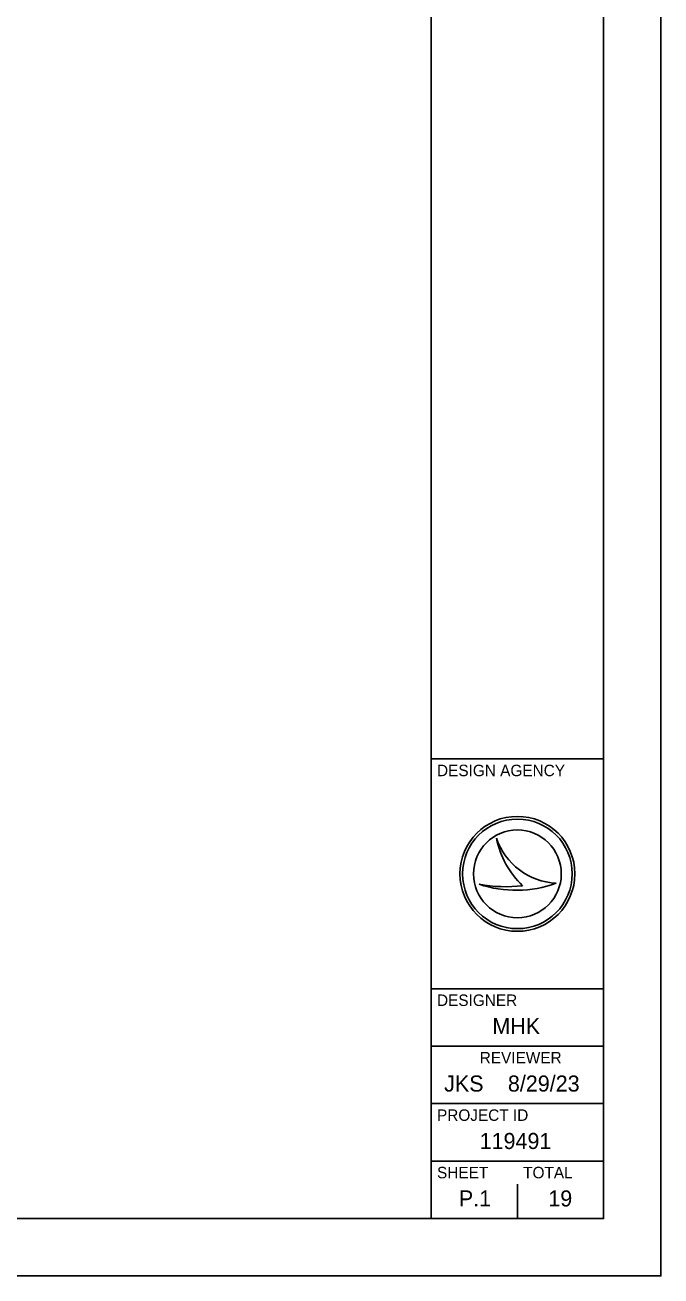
# Model space of a CAD drawing. Extents: x 0 to 34, y 0 to 22.
# Drawn here: x 28.46 to 34, y 0 to 10.89 of the extents above; entities that cross this region are included whole.
import ezdxf

# ---------------------------------------------------------------- set-up
doc = ezdxf.new("R2010")
doc.units = 0
for name, color, linetype in [('SH_Border', 7, 'Continuous'), ('SH_Cut_Line', 7, 'Continuous'), ('SH_Data', 7, 'Continuous')]:
    doc.layers.add(name, color=color, linetype=linetype)

msp = doc.modelspace()

# ---------------------------------------------------------------- linework, layer by layer
at = {"layer": 'SH_Border'}
for p, q in [((32, 0.5), (32, 21.5)), ((32, 4.5), (33.5, 4.5)), ((32, 2.5), (33.5, 2.5)), ((32, 2), (33.5, 2)), ((32, 1.5), (33.5, 1.5)), ((32, 1), (33.5, 1))]:
    msp.add_line(p, q, dxfattribs=at)
msp.add_lwpolyline([(1.5, 21.5), (33.5, 21.5), (33.5, 0.5), (1.5, 0.5)], close=True, dxfattribs=at)
at = {"layer": 'SH_Cut_Line'}
msp.add_lwpolyline([(0, 0), (34, 0), (34, 22), (0, 22)], close=True, dxfattribs=at)
at = {"layer": 'SH_Data'}
for p, q in [((32.567, 3.81), (32.567, 3.81)), ((32.75, 3.5), (32.75, 3.5)), ((32.417, 3.41), (32.417, 3.41)), ((33.087, 3.419), (33.087, 3.419)), ((32.75, 0.5), (32.75, 0.8)), ((32.375, 0.675), (32.375, 0.675))]:
    msp.add_line(p, q, dxfattribs=at)
for radius in [0.5, 0.477, 0.477, 0.382]:
    msp.add_circle((32.75, 3.5), radius, dxfattribs=at)
for centre, radius, start, end in [((33.116, 3.998), 0.58, 198.9257, 198.9319), ((33.347, 3.97), 0.796, 191.6379, 191.6421), ((33.116, 3.998), 0.58, 198.9319, 267.1657), ((33.347, 3.97), 0.796, 191.6421, 226.0947), ((32.739, 4.37), 1.013, 251.4576, 290.0832), ((32.648, 4.654), 1.266, 259.4964, 259.4995), ((32.739, 4.37), 1.013, 251.4527, 251.4576), ((32.648, 4.654), 1.266, 259.4995, 276.6672)]:
    msp.add_arc(centre, radius, start, end, dxfattribs=at)

# ---------------------------------------------------------------- texts
for s, height, p in [('DESIGN AGENCY', 0.1, (32.05, 4.35)), ('DESIGNER', 0.1, (32.05, 2.35)), ('MHK', 0.14, (32.532, 2.105)), ('REVIEWER', 0.1, (32.422, 1.85)), ('JKS', 0.14, (32.112, 1.605)), ('8/29/23', 0.14, (32.667, 1.605)), ('PROJECT ID', 0.1, (32.05, 1.35)), ('119491', 0.14, (32.421, 1.105)), ('SHEET', 0.1, (32.05, 0.85)), ('TOTAL', 0.1, (32.8, 0.85)), ('P.1', 0.14, (32.24, 0.605)), ('19', 0.14, (33.019, 0.605))]:
    msp.add_text(s, height=height, dxfattribs=at).set_placement(p)

doc.saveas('drawing.dxf')
